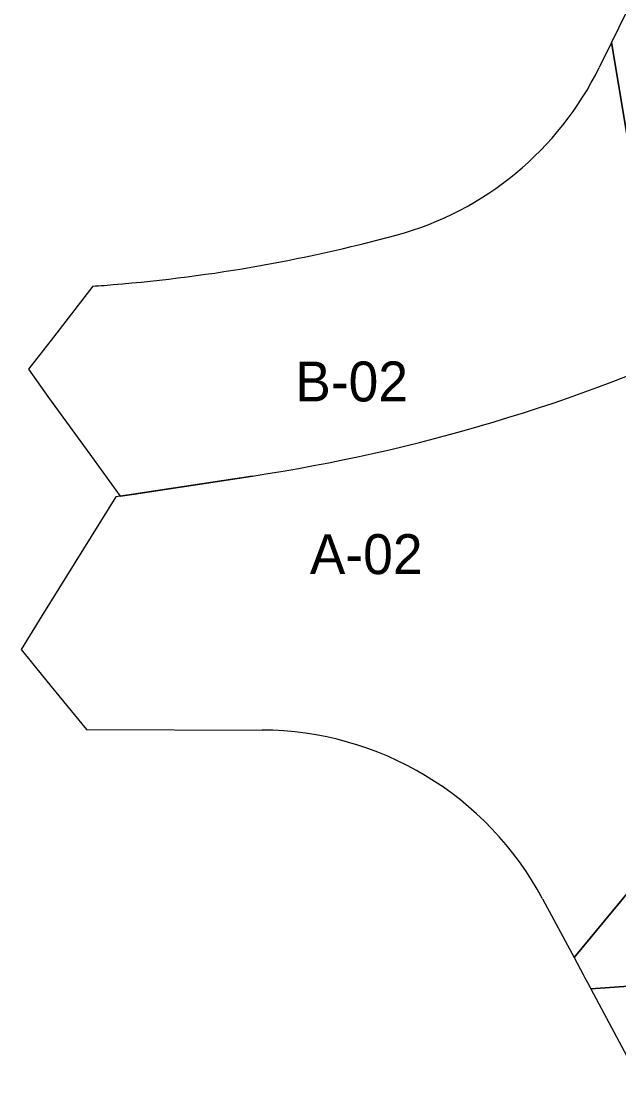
# Model space of a CAD drawing. Extents: x 5196716 to 5200291, y 3709146 to 3713154.
# Drawn here: x 5196715.8 to 5196805.6, y 3709266.9 to 3709425.2 of the extents above; entities that cross this region are included whole.
import ezdxf

# ---------------------------------------------------------------- set-up
doc = ezdxf.new("R2010")
doc.units = 0
doc.layers.add('dsnTextNote', color=7, linetype='Continuous')
doc.layers.add('Level 1', color=7, linetype='Continuous')

msp = doc.modelspace()

# ---------------------------------------------------------------- linework, layer by layer
at = {"layer": 'Level 1'}
for p, q in [((5196815.9, 3709445.18), (5196804.52, 3709421.99)), ((5196804.52, 3709421.99), (5196802.68, 3709418.24)), ((5196750.56, 3709356.87), (5196730.03, 3709353.75)), ((5196732.78, 3709354.17), (5196750.56, 3709356.87)), ((5196730.03, 3709353.75), (5196718.91, 3709335.86)), ((5196730.68, 3709353.85), (5196732.78, 3709354.17)), ((5196718.91, 3709335.86), (5196715.77, 3709330.83)), ((5196715.77, 3709330.83), (5196720.32, 3709325.27)), ((5196720.32, 3709325.27), (5196725.62, 3709318.8)), ((5196725.62, 3709318.8), (5196751.99, 3709318.72)), ((5196826.8, 3709318.28), (5196798.89, 3709284.57)), ((5196798.89, 3709284.57), (5196815.03, 3709304.07)), ((5196794.17, 3709293.38), (5196798.89, 3709284.57)), ((5196798.89, 3709284.57), (5196800.25, 3709282.02)), ((5196800.25, 3709282.02), (5196800.52, 3709281.51)), ((5196800.52, 3709281.51), (5196800.9, 3709280.81)), ((5196800.9, 3709280.81), (5196801.31, 3709280.04)), ((5196801.4, 3709279.88), (5196815.75, 3709280.89)), ((5196815.75, 3709280.89), (5196801.4, 3709279.88)), ((5196801.31, 3709280.04), (5196801.4, 3709279.88)), ((5196801.4, 3709279.88), (5196802.22, 3709278.35)), ((5196802.22, 3709278.35), (5196808.33, 3709266.93))]:
    msp.add_line(p, q, dxfattribs=at)
for points in [[(5196804.52, 3709421.99), (5196806.95, 3709407.32), (5196807.21, 3709392.52)], [(5196807.21, 3709392.52), (5196806.95, 3709407.32), (5196804.52, 3709421.99)], [(5196726.55, 3709385.39), (5196720.63, 3709377.75), (5196716.9, 3709372.93)], [(5196716.9, 3709372.93), (5196719.91, 3709368.65), (5196726.11, 3709360.14), (5196730.68, 3709353.85)]]:
    msp.add_lwpolyline(points, dxfattribs=at)
for centre, radius, start, end in [((5196759.59, 3709439.38), 48, 285.1787, 333.8681), ((5196710.5, 3709620.34), 235.5, 274.3206, 285.1787), ((5196710.5, 3709620.34), 235.5, 273.9096, 274.3206), ((5196710.5, 3709620.34), 266.5, 278.646, 294.6564), ((5196710.5, 3709620.34), 266.5, 278.646, 294.6564), ((5196751.85, 3709270.72), 48, 28.1667, 89.8345)]:
    msp.add_arc(centre, radius, start, end, dxfattribs=at)

# ---------------------------------------------------------------- texts
at = {"layer": 'dsnTextNote'}
for s, p in [('B-02', (5196756.98, 3709368.07)), ('A-02', (5196759.17, 3709342.14))]:
    msp.add_text(s, height=6, dxfattribs=at).set_placement(p)

doc.saveas('drawing.dxf')
